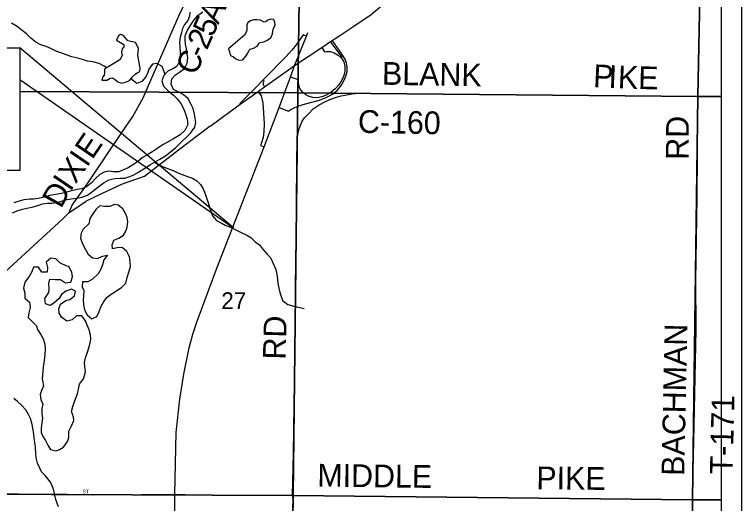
# Model space of a CAD drawing. Extents: x -784 to 1375, y -225 to 440.
# Drawn here: x 133.1 to 205.1, y 356.1 to 404.5 of the extents above; entities that cross this region are included whole.
import ezdxf

# ---------------------------------------------------------------- set-up
doc = ezdxf.new("R2010")
doc.units = 0
for name, color, linetype in [('GM_X_City_Street', 7, 'Continuous'), ('GM_X_City_Street_Text', 7, 'Continuous'), ('GM_X_County_Road', 7, 'Continuous'), ('GM_X_County_Road_Text', 7, 'Continuous'), ('GM_X_Interchange_Ramps', 7, 'Continuous'), ('GM_X_Interstate_Location', 7, 'Continuous'), ('GM_X_Interstate_Route', 7, 'Continuous'), ('GM_X_Major_River', 7, 'Continuous'), ('GM_X_Minor_Lake', 7, 'Continuous'), ('GM_X_Minor_River', 7, 'Continuous'), ('GM_X_Section', 7, 'Continuous'), ('GM_X_Section_Text', 7, 'Continuous'), ('GM_X_State_Route', 7, 'Continuous'), ('GM_X_Township_Road', 7, 'Continuous'), ('GM_X_Township_Road_Text', 7, 'Continuous'), ('SH_Data', 7, 'Continuous'), ('SH_Text', 7, 'Continuous')]:
    doc.layers.add(name, color=color, linetype=linetype)

msp = doc.modelspace()

# ---------------------------------------------------------------- linework, layer by layer
at = {"layer": 'GM_X_City_Street'}
msp.add_lwpolyline([(125.938, 357.057), (126.085, 357.057), (128.918, 357.068), (130.422, 357.063), (133.463, 357.044), (138.325, 357.009), (140.841, 356.958)], dxfattribs=at)
at = {"layer": 'GM_X_County_Road'}
for points in [[(146.605, 397.971), (146.834, 398.493), (148.809, 403.029), (149.446, 404.455), (150.224, 406.13), (151.468, 408.539), (151.66, 408.91)], [(138.526, 384.857), (138.831, 385.595), (140.061, 387.346), (140.756, 388.352), (143.751, 392.78), (144.822, 394.365), (145.835, 396.21), (146.605, 397.971)], [(141.059, 356.958), (145.671, 356.983), (148.597, 356.972)], [(148.597, 356.972), (148.994, 356.971)], [(148.994, 356.971), (149.992, 356.965)]]:
    msp.add_lwpolyline(points, dxfattribs=at)
at = {"layer": 'GM_X_Interchange_Ramps'}
for points in [[(162.004, 402.327), (161.676, 402.458), (161.388, 402.017), (161.009, 401.467), (160.577, 400.926), (160.012, 400.307), (157.737, 397.981), (157.075, 397.305), (155.408, 395.65), (155.449, 395.592)], [(159.301, 395.248), (160.227, 394.899), (160.417, 395.043), (160.725, 395.203), (161.168, 395.387), (161.927, 395.63), (163.318, 395.991), (164.048, 396.284), (164.584, 396.577), (165.044, 396.949), (165.458, 397.426), (165.732, 397.892), (165.924, 398.351), (166.039, 398.811), (166.057, 399.223), (165.988, 399.659), (165.833, 400.052), (165.493, 400.617), (164.702, 401.711), (164.577, 401.899)], [(164.393, 401.778), (164.536, 401.563), (165.523, 400.254), (165.449, 400.173)], [(163.523, 401.2), (163.816, 400.759), (163.982, 400.81), (164.402, 400.788), (164.769, 400.681), (165.167, 400.435), (165.449, 400.173), (165.48, 400.144), (165.711, 399.77), (165.831, 399.313), (165.82, 398.87), (165.702, 398.429), (165.503, 397.954), (165.208, 397.507), (164.852, 397.103), (164.431, 396.755), (163.974, 396.489), (163.549, 396.327), (163.082, 396.231), (162.642, 396.25), (162.276, 396.357), (161.966, 396.51), (161.615, 396.777), (161.372, 397.146), (161.264, 397.462), (161.22, 397.791), (161.228, 397.981), (160.428, 398.274)], [(157.737, 397.981), (157.824, 397.899), (157.781, 397.849), (157.758, 397.805), (157.738, 397.761), (157.717, 397.681), (157.715, 397.592), (157.728, 397.525), (157.747, 397.461), (157.79, 397.393), (157.836, 397.337), (157.874, 397.313)], [(157.227, 396.853), (157.545, 396.404), (157.683, 395.71), (157.774, 394.743), (157.836, 393.652), (157.804, 392.869), (157.719, 392.301), (157.567, 391.759), (157.477, 391.495), (157.84, 391.358)]]:
    msp.add_lwpolyline(points, dxfattribs=at)
at = {"layer": 'GM_X_Interstate_Route'}
for points in [[(161.281, 400.511), (161.287, 400.526), (162.004, 402.327), (162.151, 402.695)], [(160.005, 397.139), (160.428, 398.274), (160.847, 399.422), (161.281, 400.511)], [(148.956, 342.85), (148.994, 356.971), (149.127, 363.092), (149.481, 366.399), (149.866, 368.87), (150.415, 371.5), (150.759, 372.833), (151.182, 374.134), (153.143, 379.365), (157.84, 391.358), (159.301, 395.248), (160.005, 397.139)]]:
    msp.add_lwpolyline(points, dxfattribs=at)
at = {"layer": 'GM_X_Major_River'}
for points in [[(132.911, 384.852), (133.379, 385.041), (133.907, 385.199), (134.495, 385.341), (134.871, 385.396), (135.414, 385.569), (135.882, 385.728), (136.378, 385.781), (136.814, 385.806), (137.431, 385.902), (137.854, 386.032), (138.321, 386.16), (138.727, 386.23), (139.239, 386.298), (139.796, 386.381), (140.34, 386.599), (140.856, 386.997), (141.478, 387.469), (141.994, 387.853), (142.448, 388.102), (143.035, 388.229), (143.561, 388.267), (144.042, 388.275), (144.419, 388.39), (144.842, 388.58), (145.402, 388.872), (146.023, 389.254), (146.583, 389.607), (147.023, 389.872), (147.507, 390.15), (148.052, 390.473), (148.553, 390.887), (149.07, 391.315), (149.648, 391.878), (150.135, 392.337), (150.546, 392.722), (150.959, 393.302), (151.056, 393.781), (151.001, 394.187), (150.947, 394.608), (150.804, 395.151), (150.614, 395.559), (150.291, 396.119), (149.816, 396.561), (149.309, 396.808), (148.862, 397.054), (148.628, 397.568), (148.68, 398.093), (149.061, 398.493), (149.44, 398.743), (149.926, 399.112), (150.218, 399.648), (150.286, 400.218), (150.188, 400.7), (150.148, 401.076), (150.049, 401.528), (150.008, 401.904), (150.015, 402.354), (150.247, 402.906), (150.57, 403.442), (150.907, 403.918), (151.258, 404.349), (151.759, 404.717)], [(150.482, 404.675), (150.431, 404.285), (150.276, 403.882), (149.939, 403.466), (149.754, 403.078), (149.628, 402.674), (149.502, 402.226), (149.435, 401.716), (149.489, 401.265), (149.527, 400.754), (149.506, 400.289), (149.409, 399.78), (149.192, 399.302), (148.799, 399.097), (148.3, 398.864), (147.904, 398.419), (147.702, 397.911), (147.845, 397.368), (148.334, 396.896), (148.839, 396.484), (149.225, 396.133), (149.579, 395.663), (149.827, 395.149), (150.046, 394.621), (150.219, 394.108), (150.257, 393.567), (149.978, 392.97), (149.522, 392.571), (148.856, 392.144), (148.311, 391.851), (147.812, 391.603), (147.205, 391.161), (146.796, 390.896), (146.205, 390.543), (145.797, 390.309), (145.281, 389.895), (144.886, 389.63), (144.356, 389.307), (143.827, 389.059), (143.42, 388.899), (142.894, 388.907), (142.489, 388.972), (141.977, 388.874), (141.569, 388.639), (141.173, 388.269), (140.716, 387.81), (140.23, 387.396), (139.777, 387.207), (139.326, 387.153), (138.632, 386.982), (138.18, 386.853), (137.758, 386.739), (137.201, 386.656), (136.599, 386.559), (136.192, 386.43), (135.453, 386.244), (134.987, 386.191), (134.611, 386.181), (134.04, 386.128), (133.557, 386), (133.029, 385.827)]]:
    msp.add_lwpolyline(points, dxfattribs=at)
at = {"layer": 'GM_X_Minor_Lake'}
for points in [[(157.36, 401.688), (157.787, 401.752), (158.135, 401.928), (158.484, 402.163), (158.639, 402.537), (158.672, 402.791), (158.767, 403.105), (158.906, 403.419), (158.895, 403.719), (158.748, 403.961), (158.494, 404.01), (158.192, 403.894), (158.025, 403.761), (157.829, 403.704), (157.456, 403.889), (157.096, 403.939), (156.765, 403.928), (156.479, 403.842), (156.206, 403.666), (156.113, 403.442), (156.124, 403.141), (156.12, 402.886), (156.027, 402.647), (155.873, 402.409), (155.691, 402.246), (154.308, 401.049)], [(145.521, 398.826), (145.555, 399.126), (145.47, 399.533), (145.317, 400.406), (145.387, 401.111), (145.27, 401.382), (145.079, 401.685), (144.345, 401.861), (143.902, 402.377), (143.617, 402.471), (143.39, 402.339), (143.205, 401.936)], [(143.205, 401.936), (143.92, 401.491), (143.931, 401.251), (143.779, 401.057), (143.714, 400.728), (143.77, 400.397), (143.539, 399.965), (142.024, 399.054), (142.005, 398.724), (141.971, 398.469), (141.864, 398.291), (141.769, 397.962), (142.25, 397.955), (142.568, 398.146), (142.794, 398.203), (143.077, 398.019), (143.344, 397.805), (143.733, 397.65), (144.185, 397.794), (144.503, 397.939), (144.778, 398.281), (145.036, 398.533), (145.249, 398.68), (145.521, 398.826)], [(154.308, 401.049), (154.395, 400.793), (154.437, 400.597), (154.539, 400.385), (154.763, 400.292), (155.016, 400.064), (155.344, 399.939), (155.705, 399.979), (156.011, 400.35), (156.225, 400.648), (156.349, 400.916), (156.441, 401.035), (156.757, 401.121), (157.135, 401.311), (157.289, 401.564), (157.36, 401.688)], [(143.36, 385.596), (143.001, 385.676), (142.532, 385.457), (142.067, 385.464), (141.572, 385.546), (141.147, 385.176), (140.794, 384.655), (140.579, 384.268), (140.452, 383.759), (139.919, 383.21), (139.718, 382.822), (139.652, 382.343), (139.854, 381.784), (140.132, 381.225), (140.411, 380.741), (140.842, 380.389), (141.337, 380.337), (141.806, 380.541), (142.302, 380.64), (141.966, 380.194), (141.824, 379.685), (141.668, 379.267), (141.407, 378.79), (140.844, 378.287)], [(140.844, 378.287), (140.36, 378.023), (139.834, 378), (139.798, 377.535), (139.973, 377.157), (139.936, 376.632), (139.899, 376.152), (139.924, 375.776), (140.052, 375.248), (140.301, 374.734), (140.762, 374.368), (141.275, 374.571), (141.507, 375.093), (141.694, 375.602), (141.941, 376.064), (142.277, 376.48), (142.672, 376.805), (143.702, 377.452), (144.143, 377.896), (144.256, 378.45), (144.443, 378.959), (144.601, 379.527), (144.577, 380.008), (144.493, 380.49), (144.245, 381.004), (143.77, 381.416), (143.274, 381.378), (142.807, 381.294), (142.767, 381.67), (142.953, 382.133), (143.437, 382.336), (143.906, 382.63), (144.122, 383.018), (144.277, 383.406), (144.329, 383.946), (144.275, 384.368), (144.115, 384.76), (143.821, 385.245), (143.36, 385.596)], [(138.292, 379.576), (137.606, 379.908), (137.206, 380.303), (136.696, 380.34), (136.255, 379.956), (136.383, 379.444), (136.347, 378.978), (135.821, 378.986), (135.482, 379.456), (134.987, 379.478), (134.815, 379.014), (134.569, 378.537), (134.126, 377.987), (133.983, 377.389), (134.126, 376.876), (134.12, 376.395), (134.58, 375.999), (134.648, 375.487), (134.521, 374.948), (134.469, 374.483), (134.885, 374.072), (135.27, 373.676), (135.4, 373.284), (135.753, 372.738), (135.958, 372.36), (136.117, 371.862), (136.155, 371.336), (136.103, 370.826), (136.035, 370.226), (135.951, 369.566), (135.916, 369.161), (135.861, 368.426)], [(135.861, 368.426), (135.873, 368.245), (135.972, 367.733), (135.77, 367.271), (135.66, 366.866), (135.713, 366.385), (135.902, 365.902), (135.822, 365.497), (135.815, 364.987), (135.869, 364.52), (135.818, 364.07), (135.735, 363.531), (135.76, 363.155), (135.891, 362.777), (136.185, 362.323), (136.433, 361.794), (136.684, 361.415), (137.193, 361.302), (137.57, 361.417), (137.949, 361.668), (138.361, 362.203), (138.472, 362.607), (138.48, 363.253), (138.743, 363.76), (138.975, 364.298), (138.95, 364.674), (138.761, 365.187), (138.873, 365.696), (139.014, 366.085), (139.185, 366.503), (139.34, 366.921), (139.437, 367.386), (139.549, 367.895), (139.931, 368.401), (140.072, 368.834), (140.122, 369.224), (140.082, 369.6), (140.043, 370.021), (140.124, 370.486), (140.327, 371.054), (140.483, 371.487), (140.61, 371.981), (140.66, 372.386), (140.62, 372.777), (140.492, 373.275), (140.302, 373.728), (140.128, 374.166), (139.759, 374.652), (139.233, 374.659), (138.822, 374.244), (138.295, 374.116), (137.759, 374.514), (137.525, 374.922), (137.485, 375.328), (137.671, 375.791), (138.202, 376.16), (138.579, 376.26), (139.049, 376.614), (139.146, 377.093), (138.743, 377.294), (138.199, 377.091), (137.759, 376.767), (137.529, 376.364), (137.012, 375.891), (136.634, 375.685), (136.17, 375.827), (136.117, 376.368), (136.515, 376.949), (136.535, 377.324), (136.512, 377.85), (136.608, 378.269), (137.133, 378.247), (137.674, 378.255), (138.165, 377.902), (138.677, 377.971), (138.849, 378.509), (138.78, 378.975), (138.502, 379.52), (138.292, 379.576)]]:
    msp.add_lwpolyline(points, dxfattribs=at)
at = {"layer": 'GM_X_Minor_River'}
for points in [[(142.241, 399.184), (141.998, 399.355), (141.476, 399.617), (140.877, 399.761), (140.338, 399.858), (139.844, 400), (139.365, 400.141), (138.796, 400.284), (138.228, 400.457), (137.69, 400.66), (137.286, 400.815), (136.779, 401.047), (136.241, 401.28), (135.718, 401.467), (135.226, 401.729), (134.735, 402.111), (134.306, 402.538), (133.859, 402.874), (133.369, 403.256), (132.818, 403.609)], [(148.012, 398.54), (147.924, 398.779), (147.72, 399.307), (147.199, 399.615), (146.777, 399.53), (146.425, 399.054), (146.284, 398.636), (146.069, 398.248), (145.718, 397.818), (145.22, 397.644), (144.617, 398.082)], [(147.014, 389.867), (147.26, 389.643), (147.768, 389.426), (148.366, 389.208), (148.814, 389.021), (149.291, 388.805), (149.725, 388.633), (150.233, 388.431), (150.726, 388.259), (151.173, 388.013), (151.529, 387.633), (151.793, 387.209), (151.982, 386.726), (152.2, 386.137), (152.343, 385.624), (152.501, 385.112), (152.704, 384.553), (153.103, 384.097), (153.566, 383.836), (153.968, 383.605), (154.506, 383.417), (154.894, 383.217), (155.476, 382.924), (156.118, 382.615), (156.505, 382.384), (156.95, 381.972), (157.352, 381.667), (157.677, 381.272), (158.135, 380.755), (158.491, 380.345), (158.709, 379.816), (158.971, 379.242), (159.085, 378.729), (159.138, 378.248), (159.193, 377.872), (159.277, 377.375), (159.392, 376.968), (159.506, 376.546), (159.681, 376.138), (160.187, 375.786), (160.755, 375.613), (161.235, 375.501), (161.773, 375.359)], [(137.45, 355.77), (137.204, 356.495), (137.105, 356.917), (137.006, 357.384), (136.876, 357.776), (136.686, 358.185), (136.183, 358.807), (135.783, 359.218), (135.608, 359.596), (135.389, 360.065), (135.246, 360.593), (135.207, 361.074), (135.184, 361.63), (135.116, 362.142), (135.062, 362.563), (135.006, 362.94), (134.952, 363.346), (134.854, 363.903), (134.682, 364.506), (134.507, 364.899), (134.243, 365.353), (133.798, 365.825), (133.413, 366.191), (133.026, 366.467)]]:
    msp.add_lwpolyline(points, dxfattribs=at)
at = {"layer": 'GM_X_Section'}
for points in [[(161.508, 419.485), (161.159, 396.705), (133.637, 396.836)], [(201.225, 419.485), (200.783, 396.352), (161.159, 396.705), (161.508, 419.485)], [(203.088, 396.355), (200.783, 396.352), (201.225, 419.485)], [(133.637, 396.836), (161.159, 396.705), (160.697, 356.887), (120.755, 357.05), (121.281, 389.014)], [(203.088, 356.455), (200.23, 356.446), (200.783, 396.352), (203.088, 396.355)], [(203.088, 316.862), (199.773, 316.883), (200.23, 356.446), (203.088, 356.455)]]:
    msp.add_lwpolyline(points, dxfattribs=at)
for points in [[(200.783, 396.352), (200.23, 356.446), (160.697, 356.887), (161.159, 396.705)], [(120.755, 357.05), (160.697, 356.887), (159.863, 317.136), (120.146, 317.31)], [(160.697, 356.887), (200.23, 356.446), (199.773, 316.883), (199.413, 316.89), (159.863, 317.136)]]:
    msp.add_lwpolyline(points, close=True, dxfattribs=at)
at = {"layer": 'GM_X_State_Route'}
for points in [[(166.701, 403.31), (168.426, 404.455), (170.986, 406.675), (178.697, 412.562), (180.635, 414.124), (181.532, 414.933), (182.258, 415.778), (182.635, 416.335), (184.243, 419.294), (184.349, 419.485)], [(160.252, 399), (160.847, 399.422), (163.523, 401.2), (164.393, 401.778), (164.577, 401.899), (165.325, 402.397), (166.701, 403.31)], [(152.574, 393.493), (155.449, 395.592), (157.227, 396.853), (157.874, 397.313), (160.252, 399)], [(145.972, 388.454), (145.976, 388.456), (149.333, 391.07), (152.496, 393.435), (152.574, 393.493)], [(140.161, 385.97), (140.184, 385.986), (141.82, 386.775), (143.817, 387.708), (145.972, 388.454)], [(137.973, 384.32), (138.458, 384.791), (138.526, 384.857), (140.161, 385.97)], [(123.112, 370.833), (130.071, 377.093), (137.891, 384.241), (137.973, 384.32)]]:
    msp.add_lwpolyline(points, dxfattribs=at)
at = {"layer": 'GM_X_Township_Road'}
for points in [[(160.499, 348.034), (160.739, 356.287), (160.643, 356.918), (160.739, 361.018), (160.849, 370.465), (160.893, 372.549), (160.922, 377.513), (160.994, 382.4), (161.023, 385.258), (161.065, 390.258), (161.082, 391.702), (161.113, 392.25), (161.15, 392.535), (161.232, 392.967), (161.379, 393.416), (161.585, 393.891), (161.817, 394.224), (162.279, 394.713), (162.684, 395.111), (163.288, 395.515), (163.831, 395.823), (164.322, 396.066), (164.975, 396.286), (165.462, 396.413), (166, 396.521), (166.514, 396.605), (167.164, 396.662)], [(200.24, 356.391), (200.383, 362.25), (200.587, 373.309), (200.563, 378.151), (200.694, 386.412), (200.766, 394.702), (200.777, 396.128)]]:
    msp.add_lwpolyline(points, dxfattribs=at)
at = {"layer": 'SH_Data'}
msp.add_line((205.088, 421.485), (205.088, 281.485), dxfattribs=at)
at = {"layer": 'SH_Text'}
for points in [[(67.088, 419.485), (203.088, 419.485), (203.088, 283.485), (67.088, 283.485)], [(86.63, 401.16), (133.637, 401.16), (133.637, 389.014), (86.63, 389.014)], [(133.637, 398.041), (154.791, 383.351), (133.637, 401.16)]]:
    msp.add_lwpolyline(points, close=True, dxfattribs=at)

# ---------------------------------------------------------------- texts
at = {"layer": 'GM_X_City_Street_Text'}
msp.add_text('ST', height=0.375, rotation=0.00001, dxfattribs=at).set_placement((139.847, 357.076))
at = {"layer": 'GM_X_County_Road_Text'}
for s, rotation, p in [('A', 64.68293, (153.281, 403.39)), ('5', 65.97251, (152.722, 402.136)), ('2', 66.20554, (152.164, 400.87)), ('C', 66.28636, (151.05, 398.333)), ('-', 66.2705, (151.793, 400.025)), ('BLANK', 359.00847, (169.479, 397.515)), ('P', 357.52366, (190.375, 397.283)), ('I', 357.52469, (191.892, 397.217)), ('K', 357.58814, (192.817, 397.177)), ('E', 358.65422, (194.841, 397.092)), ('C-160', 358.90312, (167.096, 392.762)), ('E', 55.60271, (140.795, 390.03)), ('I', 55.60846, (140.273, 389.268)), ('X', 55.61886, (139.155, 387.634)), ('I', 55.99601, (138.64, 386.871)), ('D', 60.97759, (137.707, 385.184)), ('MIDDLE', 359.29488, (163.085, 357.763)), ('PIKE', 359.38094, (184.77, 357.499))]:
    msp.add_text(s, height=2.25, rotation=rotation, dxfattribs=at).set_placement(p)
at = {"layer": 'GM_X_Interstate_Location'}
for s in ['-', '.', ',']:
    msp.add_text(s, height=0.0075, dxfattribs=at).set_placement((153.127, 379.326))
at = {"layer": 'GM_X_Section_Text'}
msp.add_text('27', height=1.6575, rotation=0.00001, dxfattribs=at).set_placement((153.584, 375.322))
at = {"layer": 'GM_X_Township_Road_Text'}
for s, rotation, p in [('RD', 89.50446, (199.847, 390.079)), ('RD', 88.55542, (159.951, 370.299)), ('BACHMAN', 88.79251, (199.418, 358.803)), ('T-171', 88.59662, (204.207, 358.936))]:
    msp.add_text(s, height=2.25, rotation=rotation, dxfattribs=at).set_placement(p)

doc.saveas('drawing.dxf')
